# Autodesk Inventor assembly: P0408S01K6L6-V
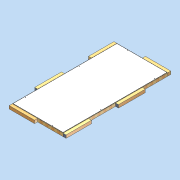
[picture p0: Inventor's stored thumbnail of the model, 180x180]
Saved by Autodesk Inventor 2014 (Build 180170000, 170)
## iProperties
Created: 2011-04
Part Number: P0408S01K6L6-V
Document SubType Name: Assembly
Designer: david.appleford
Description: 1w x 2w  01 Panel - 6 Locks 6 Lugs
Mass: 48000 g
Surface Area: 70417.3 cm^2
Volume: 234014 cm^3
Cost Center: £164.00
Density: 0.205116 g/cm^3
Justset: False
Title: 1w x 2w  01 Panel - 6 Locks 6 Lugs
Author: david.appleford
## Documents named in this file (4)
- C:\Documents and Settings\john.everitt\Local Settings\My Documents\Vault\Production MkII\VIRTUAL ELEMENTS\Virtual Walls\Virtual Timber + MgO\P0408S01K6L6-V.iam
- C:\Documents and Settings\john.everitt\Local Settings\My Documents\Vault\Production MkII\Virtual Elements\Virtual Walls\Virtual Timber + MgO\P0408S01K6-V.ipt
- C:\Documents and Settings\john.everitt\Local Settings\My Documents\Vault\Production MkII\VIRTUAL ELEMENTS\Virtual Lugs\LA02C3CC-V.ipt
- C:\Documents and Settings\john.everitt\Local Settings\My Documents\Vault\Production MkII\VIRTUAL ELEMENTS\Virtual Lugs\LA02M3CC-V.ipt
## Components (7 placed, 3 different names)
1. P0408S01K6-V:1 — Mate:1, Flush:1, Flush:2, Mate:2, Flush:3, Flush:4, Mate:4, Flush:7, Flush:8, Mate:5, Mate:6, Flush:9, Flush:10, Mate:7, Flush:11
2. LA02C3CC-V:1 — Mate:1, Flush:1, Flush:2, Mate:9, Mate:13
3. LA02C3CC-V:2 — Mate:2, Flush:3, Flush:4
4. LA02C3CC-V:3 — Mate:4, Flush:7, Flush:8
5. LA02C3CC-V:4 — Mate:6, Flush:9, Mate:12
6. LA02M3CC-V:1 — Mate:5, Flush:10, Mate:12, Mate:13
7. LA02M3CC-V:2 — Mate:7, Flush:11, Mate:9
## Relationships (18: Mate 9, Flush 9)
- Mate:1: P0408S01K6-V:1 ↔ LA02C3CC-V:1
- Flush:1: P0408S01K6-V:1 ↔ LA02C3CC-V:1
- Flush:2: P0408S01K6-V:1 ↔ LA02C3CC-V:1
- Mate:2: P0408S01K6-V:1 ↔ LA02C3CC-V:2
- Flush:3: P0408S01K6-V:1 ↔ LA02C3CC-V:2
- Flush:4: P0408S01K6-V:1 ↔ LA02C3CC-V:2
- Mate:4: P0408S01K6-V:1 ↔ LA02C3CC-V:3
- Flush:7: P0408S01K6-V:1 ↔ LA02C3CC-V:3
- Flush:8: P0408S01K6-V:1 ↔ LA02C3CC-V:3
- Mate:5: P0408S01K6-V:1 ↔ LA02M3CC-V:1
- Mate:6: P0408S01K6-V:1 ↔ LA02C3CC-V:4
- Flush:9: P0408S01K6-V:1 ↔ LA02C3CC-V:4
- Flush:10: P0408S01K6-V:1 ↔ LA02M3CC-V:1
- Mate:7: P0408S01K6-V:1 ↔ LA02M3CC-V:2
- Flush:11: P0408S01K6-V:1 ↔ LA02M3CC-V:2
- Mate:9: LA02C3CC-V:1 ↔ LA02M3CC-V:2
- Mate:12: LA02C3CC-V:4 ↔ LA02M3CC-V:1
- Mate:13: LA02C3CC-V:1 ↔ LA02M3CC-V:1
## Named parameters: t = 1 mm, Cl = 2 mm
